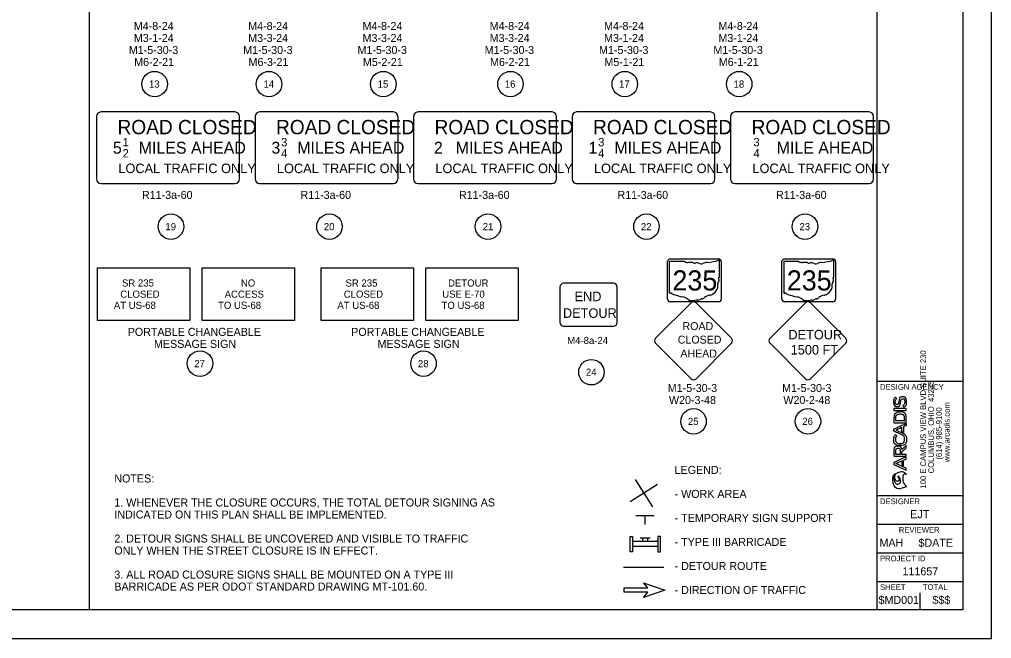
# Model space of a CAD drawing. Extents: x 632.2 to 666.2, y -36.3 to -14.3.
# Drawn here: x 649.19 to 666.19, y -36.3 to -25.48 of the extents above; entities that cross this region are included whole.
import ezdxf

# ---------------------------------------------------------------- set-up
doc = ezdxf.new("R2010")
doc.units = 0
for name, color, linetype in [('Default', 7, 'Continuous'), ('GM_X_County_Subdivision_Text', 7, 'Continuous'), ('GM_X_Township_Subdivision', 7, 'Continuous'), ('MT_P_Cells', 7, 'Continuous'), ('SH_Border', 7, 'Continuous'), ('SH_Cut_Line', 7, 'Continuous'), ('SH_Data', 7, 'Continuous'), ('SH_Text', 7, 'Continuous'), ('SN_P_Signs', 7, 'Continuous'), ('SN_P_Text', 7, 'Continuous')]:
    doc.layers.add(name, color=color, linetype=linetype)

msp = doc.modelspace()

# ---------------------------------------------------------------- linework, layer by layer
at = {"layer": 'Default'}
for centre in [(651.551, -26.606), (653.551, -26.606), (655.551, -26.606), (657.774, -26.606), (659.774, -26.606), (661.774, -26.606), (651.837, -29.098), (654.609, -29.098), (657.381, -29.098), (660.153, -29.098), (662.925, -29.098), (652.345, -31.494), (656.254, -31.494), (659.19, -31.644), (660.976, -32.504), (662.976, -32.504)]:
    msp.add_circle(centre, 0.223, dxfattribs=at)
at = {"layer": 'GM_X_County_Subdivision_Text'}
for p, q in [((660.345, -33.608), (659.866, -33.912)), ((659.953, -33.521), (660.257, -34)), ((660.105, -33.76), (660.105, -33.76))]:
    msp.add_line(p, q, dxfattribs=at)
at = {"layer": 'GM_X_Township_Subdivision'}
for p, q in [((660.174, -35.418), (660.099, -35.326)), ((660.099, -35.326), (660.474, -35.456)), ((659.761, -35.493), (659.761, -35.418)), ((659.761, -35.418), (660.174, -35.418)), ((659.761, -35.456), (659.761, -35.456)), ((660.174, -35.493), (659.761, -35.493)), ((660.474, -35.456), (660.099, -35.586)), ((660.099, -35.586), (660.174, -35.493)), ((660.474, -35.456), (660.474, -35.456))]:
    msp.add_line(p, q, dxfattribs=at)
at = {"layer": 'MT_P_Cells'}
for p, q in [((660.354, -34.605), (659.909, -34.605)), ((660.042, -34.538), (660.22, -34.538)), ((660.087, -34.605), (660.087, -34.538)), ((660.131, -34.649), (660.131, -34.649)), ((660.176, -34.605), (660.176, -34.538)), ((660.354, -34.694), (659.909, -34.694))]:
    msp.add_line(p, q, dxfattribs=at)
for points in [[(659.865, -34.783), (659.865, -34.516), (659.909, -34.516), (659.909, -34.783)], [(660.398, -34.783), (660.398, -34.516), (660.354, -34.516), (660.354, -34.783)]]:
    msp.add_lwpolyline(points, close=True, dxfattribs=at)
at = {"layer": 'SH_Border'}
for p, q in [((664.187, -35.802), (664.187, -14.802)), ((664.187, -31.802), (665.687, -31.802)), ((664.187, -33.802), (665.687, -33.802)), ((664.187, -34.302), (665.687, -34.302)), ((664.187, -34.802), (665.687, -34.802)), ((664.187, -35.302), (665.687, -35.302))]:
    msp.add_line(p, q, dxfattribs=at)
msp.add_lwpolyline([(633.687, -14.802), (665.687, -14.802), (665.687, -35.802), (633.687, -35.802)], close=True, dxfattribs=at)
at = {"layer": 'SH_Cut_Line'}
msp.add_lwpolyline([(632.187, -36.302), (666.187, -36.302), (666.187, -14.302), (632.187, -14.302)], close=True, dxfattribs=at)
at = {"layer": 'SH_Data'}
for p, q in [((664.695, -32.28), (664.479, -32.28)), ((664.479, -32.28), (664.479, -32.314)), ((664.695, -32.314), (664.695, -32.28)), ((664.479, -32.314), (664.695, -32.314)), ((664.937, -32.802), (664.937, -32.802)), ((664.937, -32.802), (664.937, -32.802)), ((664.695, -33.127), (664.479, -33.223)), ((664.695, -33.164), (664.695, -33.127)), ((664.479, -33.223), (664.479, -33.261)), ((664.479, -33.261), (664.695, -33.358)), ((664.516, -33.242), (664.618, -33.197)), ((664.695, -33.321), (664.516, -33.242)), ((664.618, -33.197), (664.618, -33.268)), ((664.618, -33.268), (664.65, -33.282)), ((664.65, -33.183), (664.695, -33.164)), ((664.65, -33.282), (664.65, -33.183)), ((664.695, -33.358), (664.695, -33.321)), ((664.937, -35.802), (664.937, -35.502)), ((664.562, -35.627), (664.562, -35.627))]:
    msp.add_line(p, q, dxfattribs=at)
for points, degree in [([(664.527, -32.109), (664.512, -32.119), (664.503, -32.14), (664.503, -32.162), (664.503, -32.191), (664.515, -32.212), (664.536, -32.212), (664.557, -32.212), (664.563, -32.188), (664.567, -32.16), (664.573, -32.115), (664.585, -32.073), (664.633, -32.073), (664.682, -32.073), (664.7, -32.117), (664.7, -32.162), (664.7, -32.204), (664.687, -32.235), (664.651, -32.255), (664.651, -32.255), (664.634, -32.229), (664.634, -32.229), (664.66, -32.214), (664.669, -32.187), (664.669, -32.162), (664.669, -32.136), (664.66, -32.108), (664.633, -32.108), (664.61, -32.108), (664.602, -32.133), (664.598, -32.163), (664.592, -32.205), (664.581, -32.246), (664.535, -32.246), (664.49, -32.246), (664.473, -32.202), (664.473, -32.163), (664.473, -32.132), (664.481, -32.101), (664.51, -32.083), (664.51, -32.083), (664.527, -32.109), (664.527, -32.109), (664.527, -32.109), (664.527, -32.109), (664.527, -32.109)], 3), ([(664.479, -32.53), (664.479, -32.53), (664.695, -32.53), (664.695, -32.53), (664.695, -32.53), (664.695, -32.448), (664.695, -32.448), (664.695, -32.373), (664.64, -32.339), (664.585, -32.34), (664.532, -32.341), (664.479, -32.375), (664.479, -32.448)], 3), ([(664.479, -32.448), (664.479, -32.448), (664.479, -32.53), (664.479, -32.53)], 2), ([(664.512, -32.496), (664.512, -32.496), (664.512, -32.448), (664.512, -32.448), (664.512, -32.398), (664.549, -32.376), (664.585, -32.375), (664.623, -32.374), (664.662, -32.396), (664.662, -32.448), (664.662, -32.448), (664.662, -32.496), (664.662, -32.496)], 3), ([(664.479, -32.639), (664.479, -32.639), (664.479, -32.676), (664.479, -32.676), (664.479, -32.676), (664.619, -32.739), (664.619, -32.739), (664.619, -32.739), (664.619, -32.739), (664.619, -32.739), (664.632, -32.746), (664.641, -32.753), (664.644, -32.756), (664.659, -32.771), (664.667, -32.793), (664.667, -32.813), (664.667, -32.868), (664.628, -32.892), (664.588, -32.892), (664.549, -32.892), (664.508, -32.867), (664.508, -32.813), (664.508, -32.793), (664.515, -32.772), (664.53, -32.757), (664.53, -32.757), (664.508, -32.734), (664.508, -32.734), (664.486, -32.756), (664.476, -32.784), (664.476, -32.813), (664.476, -32.89), (664.532, -32.926), (664.589, -32.926), (664.645, -32.926), (664.699, -32.891), (664.699, -32.813), (664.699, -32.782), (664.689, -32.754), (664.667, -32.732), (664.667, -32.732), (664.653, -32.718), (664.633, -32.709), (664.633, -32.709), (664.627, -32.706), (664.627, -32.706), (664.627, -32.706), (664.613, -32.7), (664.613, -32.7), (664.613, -32.7), (664.613, -32.7), (664.613, -32.7), (664.613, -32.7), (664.516, -32.657), (664.516, -32.657), (664.516, -32.657), (664.618, -32.612), (664.618, -32.612), (664.618, -32.612), (664.618, -32.684), (664.618, -32.684), (664.618, -32.684), (664.65, -32.697), (664.65, -32.697), (664.65, -32.697), (664.65, -32.599), (664.65, -32.599), (664.65, -32.599), (664.695, -32.579), (664.695, -32.579), (664.695, -32.579), (664.695, -32.542), (664.695, -32.542), (664.695, -32.542), (664.479, -32.639), (664.479, -32.639), (664.479, -32.639), (664.479, -32.639), (664.479, -32.639)], 3), ([(664.662, -32.496), (664.662, -32.496), (664.512, -32.496), (664.512, -32.496)], 2), ([(664.617, -32.997), (664.611, -32.955), (664.581, -32.939), (664.55, -32.939), (664.514, -32.939), (664.479, -32.965), (664.479, -33.015), (664.479, -33.048), (664.479, -33.081), (664.479, -33.115), (664.479, -33.115), (664.695, -33.115), (664.695, -33.115), (664.695, -33.115), (664.695, -33.081), (664.695, -33.081), (664.695, -33.081), (664.62, -33.081), (664.62, -33.081), (664.62, -33.081), (664.62, -33.035), (664.62, -33.035), (664.62, -33.035), (664.695, -32.969), (664.695, -32.969), (664.695, -32.969), (664.695, -32.929), (664.695, -32.929)], 3), ([(664.511, -33.015), (664.511, -32.986), (664.531, -32.974), (664.55, -32.974), (664.571, -32.974), (664.589, -32.986), (664.589, -33.015), (664.589, -33.015), (664.589, -33.081), (664.589, -33.081), (664.589, -33.081), (664.511, -33.081), (664.511, -33.081)], 3), ([(664.695, -32.929), (664.695, -32.929), (664.617, -32.997), (664.617, -32.997)], 2), ([(664.511, -33.081), (664.511, -33.081), (664.511, -33.015), (664.511, -33.015)], 2), ([(664.46, -33.516), (664.469, -33.728), (664.702, -33.646), (664.702, -33.646), (664.682, -33.628), (664.634, -33.568), (664.633, -33.485), (664.633, -33.485), (664.633, -33.485), (664.633, -33.485), (664.633, -33.445), (664.668, -33.421), (664.702, -33.43), (664.702, -33.43), (664.628, -33.367), (664.545, -33.402), (664.517, -33.414), (664.496, -33.445), (664.496, -33.482), (664.496, -33.494), (664.498, -33.507), (664.504, -33.52), (664.516, -33.55), (664.544, -33.555), (664.557, -33.548), (664.566, -33.544), (664.571, -33.535), (664.571, -33.525), (664.571, -33.523), (664.57, -33.522), (664.57, -33.52), (664.565, -33.489), (664.551, -33.477), (664.551, -33.47), (664.551, -33.469), (664.551, -33.468), (664.552, -33.467), (664.556, -33.462), (664.57, -33.467), (664.586, -33.506), (664.59, -33.516), (664.594, -33.533), (664.594, -33.55), (664.594, -33.57), (664.588, -33.59), (664.568, -33.597), (664.53, -33.609), (664.485, -33.565), (664.48, -33.498), (664.48, -33.495), (664.48, -33.49), (664.48, -33.487), (664.48, -33.453), (664.495, -33.429), (664.505, -33.417), (664.482, -33.431), (664.461, -33.46), (664.46, -33.507), (664.46, -33.507), (664.46, -33.51), (664.46, -33.516), (664.46, -33.516), (664.46, -33.516), (664.46, -33.516)], 3)]:
    msp.add_open_spline(points, degree=degree, dxfattribs=at)
at = {"layer": 'SH_Text'}
for p, q in [((650.412, -35.802), (650.412, -14.802)), ((660.459, -35.058), (659.75, -35.058))]:
    msp.add_line(p, q, dxfattribs=at)
for points in [[(650.554, -29.82), (652.169, -29.82), (652.169, -30.74), (650.554, -30.74)], [(652.384, -29.82), (653.998, -29.82), (653.998, -30.74), (652.384, -30.74)], [(654.463, -29.82), (656.078, -29.82), (656.078, -30.74), (654.463, -30.74)], [(656.293, -29.82), (657.907, -29.82), (657.907, -30.74), (656.293, -30.74)]]:
    msp.add_lwpolyline(points, close=True, dxfattribs=at)
for points in [[(660.313, -31.051), (660.932, -30.432)], [(661.02, -30.432), (661.639, -31.051)], [(660.932, -31.758), (660.313, -31.139)], [(661.639, -31.139), (661.02, -31.758)]]:
    msp.add_lwpolyline(points, dxfattribs=at)
for centre, start, end in [((660.976, -30.476), 45, 135), ((660.357, -31.095), 135, 225), ((661.594, -31.095), 315, 45), ((660.976, -31.714), 225, 315)]:
    msp.add_arc(centre, 0.0625, start, end, dxfattribs=at)
at = {"layer": 'SN_P_Signs'}
for p, q in [((660.552, -29.719), (660.552, -30.253)), ((660.818, -29.71), (660.56, -29.71)), ((661.431, -29.976), (661.431, -29.697)), ((662.552, -29.719), (662.552, -30.253)), ((662.818, -29.71), (662.56, -29.71)), ((663.431, -29.976), (663.431, -29.697)), ((661.43, -29.976), (661.431, -29.976)), ((663.43, -29.976), (663.431, -29.976)), ((659.965, -34.149), (660.285, -34.149)), ((660.125, -34.149), (660.125, -34.309))]:
    msp.add_line(p, q, dxfattribs=at)
for points in [[(650.536, -27.172), (650.536, -28.265)], [(652.957, -27.094), (650.614, -27.094)], [(653.036, -28.265), (653.036, -27.172)], [(653.308, -27.172), (653.308, -28.265)], [(655.729, -27.094), (653.386, -27.094)], [(655.808, -28.265), (655.808, -27.172)], [(656.079, -27.172), (656.079, -28.265)], [(658.501, -27.094), (656.158, -27.094)], [(658.579, -28.265), (658.579, -27.172)], [(658.851, -27.172), (658.851, -28.265)], [(661.273, -27.094), (658.93, -27.094)], [(661.351, -28.265), (661.351, -27.172)], [(661.623, -27.172), (661.623, -28.265)], [(664.045, -27.094), (661.701, -27.094)], [(664.123, -28.265), (664.123, -27.172)], [(650.614, -28.344), (652.957, -28.344)], [(653.386, -28.344), (655.729, -28.344)], [(656.158, -28.344), (658.501, -28.344)], [(658.93, -28.344), (661.273, -28.344)], [(661.701, -28.344), (664.045, -28.344)], [(660.522, -30.367), (660.522, -29.711)], [(660.569, -29.664), (661.413, -29.664)], [(661.46, -29.711), (661.46, -30.367)], [(662.522, -30.367), (662.522, -29.711)], [(662.569, -29.664), (663.413, -29.664)], [(663.46, -29.711), (663.46, -30.367)], [(659.574, -30.09), (658.704, -30.09)], [(658.639, -30.155), (658.639, -30.775)], [(659.639, -30.775), (659.639, -30.155)], [(661.413, -30.414), (660.569, -30.414)], [(663.413, -30.414), (662.569, -30.414)], [(662.313, -31.051), (662.932, -30.432)], [(663.02, -30.432), (663.639, -31.051)], [(658.704, -30.84), (659.574, -30.84)], [(662.932, -31.758), (662.313, -31.139)], [(663.639, -31.139), (663.02, -31.758)]]:
    msp.add_lwpolyline(points, dxfattribs=at)
for centre, radius, start, end in [((650.614, -27.172), 0.0781, 90, 180), ((652.957, -27.172), 0.0781, 0, 90), ((653.386, -27.172), 0.0781, 90, 180), ((655.729, -27.172), 0.0781, 0, 90), ((656.158, -27.172), 0.0781, 90, 180), ((658.501, -27.172), 0.0781, 0, 90), ((658.93, -27.172), 0.0781, 90, 180), ((661.273, -27.172), 0.0781, 0, 90), ((661.701, -27.172), 0.0781, 90, 180), ((664.045, -27.172), 0.0781, 0, 90), ((650.614, -28.265), 0.0781, 180, 270), ((652.957, -28.265), 0.0781, 270, 0), ((653.386, -28.265), 0.0781, 180, 270), ((655.729, -28.265), 0.0781, 270, 0), ((656.158, -28.265), 0.0781, 180, 270), ((658.501, -28.265), 0.0781, 270, 0), ((658.93, -28.265), 0.0781, 180, 270), ((661.273, -28.265), 0.0781, 270, 0), ((661.701, -28.265), 0.0781, 180, 270), ((664.045, -28.265), 0.0781, 270, 0), ((660.569, -29.711), 0.0469, 90, 180), ((661.413, -29.711), 0.0469, 0, 90), ((662.569, -29.711), 0.0469, 90, 180), ((663.413, -29.711), 0.0469, 0, 90), ((658.704, -30.155), 0.065, 90, 180), ((659.574, -30.155), 0.065, 0, 90), ((660.569, -30.367), 0.0469, 180, 270), ((661.413, -30.367), 0.0469, 270, 0), ((662.569, -30.367), 0.0469, 180, 270), ((662.976, -30.476), 0.0625, 45, 135), ((663.413, -30.367), 0.0469, 270, 0), ((658.704, -30.775), 0.065, 180, 270), ((659.574, -30.775), 0.065, 270, 0), ((662.357, -31.095), 0.0625, 135, 225), ((663.594, -31.095), 0.0625, 315, 45), ((662.976, -31.714), 0.0625, 225, 315)]:
    msp.add_arc(centre, radius, start, end, dxfattribs=at)
for centre, major_axis, start_param, end_param in [((660.562, -29.718), (0.0102, 0), 1.712693, 3.28349), ((660.879, -29.648), (0.0988, 0), 4.042523, 4.731795), ((660.912, -30.009), (0.355, 0), 1.404758, 1.657858), ((660.992, -29.715), (0.0285, 0), 3.836095, 5.185415), ((661.034, -29.777), (0.0592, 0), 0.950623, 2.079405), ((661.111, -29.692), (0.0713, 0), 4.081561, 5.145723), ((661.236, -29.873), (0.188, 0), 1.699011, 2.107814), ((661.117, -28.982), (0.932, 0), 4.814394, 5.042369), ((661.421, -29.695), (0.00978, 0), 6.141152, 7.989035), ((662.562, -29.718), (0.0102, 0), 1.712693, 3.28349), ((662.879, -29.648), (0.0988, 0), 4.042523, 4.731795), ((662.912, -30.009), (0.355, 0), 1.404758, 1.657858), ((662.992, -29.715), (0.0285, 0), 3.836095, 5.185415), ((663.034, -29.777), (0.0592, 0), 0.950623, 2.079405), ((663.111, -29.692), (0.0713, 0), 4.081561, 5.145723), ((663.236, -29.873), (0.188, 0), 1.699011, 2.107814), ((663.117, -28.982), (0.932, 0), 4.814394, 5.042369), ((663.421, -29.695), (0.00978, 0), 6.141152, 7.989035), ((661.466, -30.093), (0.0661, 0), 2.387724, 3.262537), ((661.428, -29.996), (0.0151, 0), 1.883978, 3.671073), ((661.332, -30.031), (0.0909, 0), 5.934695, 6.695948), ((661.42, -29.977), (0.0105, 0), 5.05454, 6.418171), ((663.466, -30.093), (0.0661, 0), 2.387724, 3.262537), ((663.428, -29.996), (0.0151, 0), 1.883978, 3.671073), ((663.332, -30.031), (0.0909, 0), 5.934695, 6.695948), ((663.42, -29.977), (0.0105, 0), 5.05454, 6.418171), ((660.562, -30.254), (0.0103, 0), 3.00124, 4.508301), ((661.17, -30.128), (0.233, 0), 5.101752, 6.440018), ((662.562, -30.254), (0.0103, 0), 3.00124, 4.508301), ((663.17, -30.128), (0.233, 0), 5.101752, 6.440018), ((660.563, -30.199), (0.0784, 0), 4.665946, 4.897461), ((660.579, -30.283), (0.0283, 0), 0.519207, 1.627899), ((660.936, -29.804), (0.673, 0), 4.195997, 4.488961), ((660.736, -30.492), (0.211, 0), 0.823519, 1.323587), ((660.963, -30.286), (0.134, 0), 4.026481, 4.996735), ((661.041, -30.471), (0.11, 0), 1.495662, 1.94098), ((661.05, -30.326), (0.0712, 0), 4.691044, 5.507374), ((661.115, -30.378), (0.02, 0), 1.147584, 2.315152), ((661.106, -30.304), (0.0753, 0), 4.937069, 5.64225), ((661.268, -30.402), (0.128, 0), 1.647645, 2.488434), ((662.563, -30.199), (0.0784, 0), 4.665946, 4.897461), ((662.579, -30.283), (0.0283, 0), 0.519207, 1.627899), ((662.936, -29.804), (0.673, 0), 4.195997, 4.488961), ((662.736, -30.492), (0.211, 0), 0.823519, 1.323587), ((662.963, -30.286), (0.134, 0), 4.026481, 4.996735), ((663.041, -30.471), (0.11, 0), 1.495662, 1.94098), ((663.05, -30.326), (0.0712, 0), 4.691044, 5.507374), ((663.115, -30.378), (0.02, 0), 1.147584, 2.315152), ((663.106, -30.304), (0.0753, 0), 4.937069, 5.64225), ((663.268, -30.402), (0.128, 0), 1.647645, 2.488434)]:
    msp.add_ellipse(centre, major_axis=major_axis, ratio=0.8, start_param=start_param, end_param=end_param, dxfattribs=at)

# ---------------------------------------------------------------- texts
at = {"layer": 'Default'}
for s, p in [('13', (651.453, -26.668)), ('14', (653.455, -26.668)), ('15', (655.452, -26.668)), ('16', (657.676, -26.668)), ('17', (659.673, -26.668)), ('18', (661.676, -26.668)), ('19', (651.74, -29.161)), ('20', (654.511, -29.161)), ('21', (657.29, -29.161)), ('22', (660.055, -29.161)), ('23', (662.828, -29.161)), ('27', (652.245, -31.557)), ('28', (656.156, -31.557)), ('24', (659.094, -31.706)), ('25', (660.877, -32.566)), ('26', (662.878, -32.566))]:
    msp.add_text(s, height=0.125, dxfattribs=at).set_placement(p)
at = {"layer": 'SH_Data'}
for s, p in [('100 E CAMPUS VIEW BLVD SUITE 230', (665.042, -33.679)), ('COLUMBUS, OHIO  43235', (665.18, -33.413)), ('(614) 985-9100', (665.318, -33.173)), ('www.arcadis.com', (665.455, -33.217))]:
    msp.add_text(s, height=0.1, rotation=90, dxfattribs=at).set_placement(p)
for s, height, p in [('DESIGN AGENCY', 0.1, (664.237, -31.952)), ('DESIGNER', 0.1, (664.237, -33.952)), ('EJT', 0.14, (664.766, -34.197)), ('REVIEWER', 0.1, (664.566, -34.452)), ('MAH', 0.14, (664.228, -34.697)), ('$DATE', 0.14, (664.91, -34.697)), ('PROJECT ID', 0.1, (664.237, -34.952)), ('111657', 0.14, (664.63, -35.197)), ('SHEET', 0.1, (664.237, -35.452)), ('TOTAL', 0.1, (664.987, -35.452)), ('$MD001', 0.14, (664.211, -35.697)), ('$$$', 0.14, (665.154, -35.697))]:
    msp.add_text(s, height=height, dxfattribs=at).set_placement(p)
at = {"layer": 'SH_Text'}
for s, height, p in [('SR 235', 0.125, (650.981, -30.147)), ('NO', 0.125, (653.061, -30.147)), ('SR 235', 0.125, (654.89, -30.147)), ('DETOUR', 0.125, (656.683, -30.147)), ('CLOSED', 0.125, (650.951, -30.342)), ('ACCESS', 0.125, (652.776, -30.342)), ('CLOSED', 0.125, (654.859, -30.342)), ('USE E-70', 0.125, (656.581, -30.342)), ('AT US-68', 0.125, (650.839, -30.537)), ('TO US-68', 0.125, (652.661, -30.537)), ('AT US-68', 0.125, (654.748, -30.537)), ('TO US-68', 0.125, (656.569, -30.537)), ('ROAD', 0.1389, (660.783, -30.908)), ('CLOSED', 0.1389, (660.7, -31.144)), ('AHEAD', 0.1389, (660.745, -31.387)), ('LEGEND:', 0.14, (660.645, -33.423)), ('NOTES:', 0.14, (650.847, -33.573)), ('- WORK AREA', 0.14, (660.645, -33.843)), ('1. WHENEVER THE CLOSURE OCCURS, THE TOTAL DETOUR SIGNING AS ', 0.14, (650.847, -33.993)), ('INDICATED ON THIS PLAN SHALL BE IMPLEMENTED.', 0.14, (650.847, -34.203)), ('- TEMPORARY SIGN SUPPORT', 0.14, (660.645, -34.263)), ('2. DETOUR SIGNS SHALL BE UNCOVERED AND VISIBLE TO TRAFFIC ', 0.14, (650.847, -34.623)), ('- TYPE III BARRICADE', 0.14, (660.645, -34.683)), ('ONLY WHEN THE STREET CLOSURE IS IN EFFECT.', 0.14, (650.847, -34.833)), ('- DETOUR ROUTE', 0.14, (660.645, -35.103)), ('3. ALL ROAD CLOSURE SIGNS SHALL BE MOUNTED ON A TYPE III ', 0.14, (650.847, -35.253)), ('BARRICADE AS PER ODOT STANDARD DRAWING MT-101.60.', 0.14, (650.847, -35.463)), ('- DIRECTION OF TRAFFIC', 0.14, (660.645, -35.523))]:
    msp.add_text(s, height=height, dxfattribs=at).set_placement(p)
at = {"layer": 'SN_P_Signs'}
for s, height, p in [('ROAD CLOSED', 0.25, (650.902, -27.483)), ('ROAD CLOSED', 0.25, (653.674, -27.483)), ('ROAD CLOSED', 0.25, (656.446, -27.483)), ('ROAD CLOSED', 0.25, (659.218, -27.483)), ('ROAD CLOSED', 0.25, (661.99, -27.483)), ('5 ', 0.2083, (650.822, -27.823)), ('1', 0.146, (650.992, -27.694)), ('MILES AHEAD', 0.20833, (651.274, -27.823)), ('3 ', 0.2083, (653.594, -27.823)), ('3', 0.146, (653.764, -27.694)), ('MILES AHEAD', 0.20833, (654.046, -27.823)), ('2', 0.208, (656.436, -27.823)), ('MILES AHEAD', 0.20833, (656.818, -27.823)), ('1 ', 0.2083, (659.138, -27.823)), ('3', 0.146, (659.308, -27.694)), ('MILES AHEAD', 0.20833, (659.59, -27.823)), ('3', 0.146, (662.023, -27.694)), ('MILE AHEAD', 0.2083, (662.43, -27.823)), ('2', 0.146, (650.992, -27.889)), ('4', 0.146, (653.764, -27.889)), ('4', 0.146, (659.308, -27.889)), ('4', 0.146, (662.023, -27.889)), ('LOCAL TRAFFIC ONLY', 0.16667, (650.918, -28.163)), ('LOCAL TRAFFIC ONLY', 0.16667, (653.69, -28.163)), ('LOCAL TRAFFIC ONLY', 0.16667, (656.462, -28.163)), ('LOCAL TRAFFIC ONLY', 0.16667, (659.234, -28.163)), ('LOCAL TRAFFIC ONLY', 0.16667, (662.006, -28.163)), ('235', 0.3516, (660.607, -30.215)), ('235', 0.3516, (662.607, -30.215)), ('END', 0.1667, (658.895, -30.403)), ('DETOUR', 0.1667, (658.692, -30.694)), ('DETOUR', 0.1667, (662.634, -31.071)), ('1500 FT', 0.1667, (662.674, -31.335))]:
    msp.add_text(s, height=height, dxfattribs=at).set_placement(p)
at = {"layer": 'SN_P_Text'}
for s, height, p in [('M4-8-24', 0.14, (651.188, -25.66)), ('M4-8-24', 0.14, (653.188, -25.66)), ('M4-8-24', 0.14, (655.188, -25.66)), ('M4-8-24', 0.14, (657.411, -25.66)), ('M4-8-24', 0.14, (659.411, -25.66)), ('M4-8-24', 0.14, (661.411, -25.66)), ('M3-1-24', 0.14, (651.188, -25.87)), ('M3-3-24', 0.14, (653.188, -25.87)), ('M3-3-24', 0.14, (655.188, -25.87)), ('M3-3-24', 0.14, (657.411, -25.87)), ('M3-1-24', 0.14, (659.411, -25.87)), ('M3-1-24', 0.14, (661.411, -25.87)), ('M1-5-30-3', 0.14, (651.1, -26.08)), ('M1-5-30-3', 0.14, (653.1, -26.08)), ('M1-5-30-3', 0.14, (655.1, -26.08)), ('M1-5-30-3', 0.14, (657.323, -26.08)), ('M1-5-30-3', 0.14, (659.323, -26.08)), ('M1-5-30-3', 0.14, (661.323, -26.08)), ('M6-2-21', 0.14, (651.194, -26.29)), ('M6-3-21', 0.14, (653.194, -26.29)), ('M5-2-21', 0.14, (655.194, -26.29)), ('M6-2-21', 0.14, (657.417, -26.29)), ('M5-1-21', 0.14, (659.417, -26.29)), ('M6-1-21', 0.14, (661.417, -26.29)), ('R11-3a-60', 0.14, (651.33, -28.614)), ('R11-3a-60', 0.14, (654.102, -28.614)), ('R11-3a-60', 0.14, (656.874, -28.614)), ('R11-3a-60', 0.14, (659.646, -28.614)), ('R11-3a-60', 0.14, (662.418, -28.614)), ('PORTABLE CHANGEABLE ', 0.14, (651.081, -31.009)), ('PORTABLE CHANGEABLE ', 0.14, (654.989, -31.009)), ('MESSAGE SIGN', 0.14, (651.541, -31.219)), ('MESSAGE SIGN', 0.14, (655.449, -31.219)), ('M4-8a-24', 0.125, (658.766, -31.152)), ('M1-5-30-3', 0.14, (660.525, -31.991)), ('M1-5-30-3', 0.14, (662.525, -31.991)), ('W20-3-48', 0.14, (660.546, -32.201)), ('W20-2-48', 0.14, (662.546, -32.201))]:
    msp.add_text(s, height=height, dxfattribs=at).set_placement(p)

doc.saveas('drawing.dxf')
